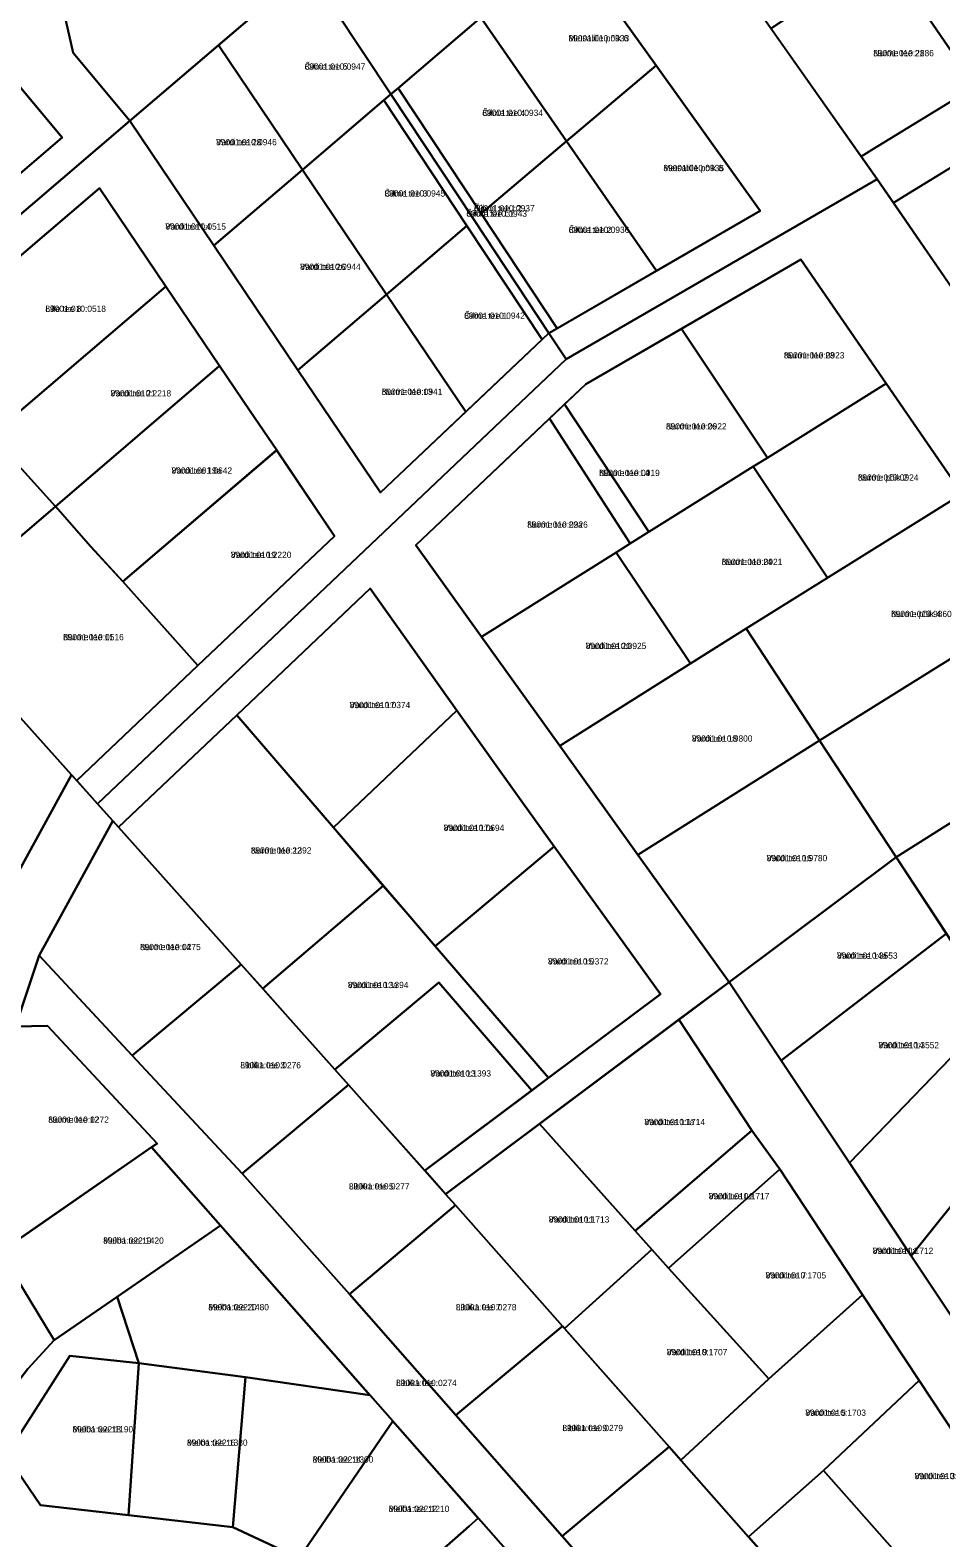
# Model space of a CAD drawing. Extents: x 526849 to 562296, y 6591741 to 6618546.
# Drawn here: x 546028.2 to 546246.1, y 6598458.8 to 6598819.9 of the extents above; entities that cross this region are included whole.
import ezdxf

# ---------------------------------------------------------------- set-up
doc = ezdxf.new("R2010")
doc.units = 0
for name, color, linetype in [('L_AADRESS', 7, 'Continuous'), ('PIIR', 7, 'Continuous'), ('TUNNUS', 7, 'Continuous')]:
    doc.layers.add(name, color=color, linetype=linetype)

msp = doc.modelspace()

# ---------------------------------------------------------------- linework, layer by layer
at = {"layer": 'PIIR'}
for points in [[(546227.01, 6598789.61), (546229.57, 6598791.18), (546282.53, 6598823.65), (546327.15, 6598851.02), (546371.97, 6598878.5), (546413.8, 6598904.15), (546446.52, 6598936.13), (546471.16, 6598923.58), (546475.1, 6598905.89), (546459.53, 6598913.79), (546427, 6598896.41), (546382.82, 6598869.32), (546336.26, 6598840.76), (546290.19, 6598812.52), (546237.29, 6598780.08), (546234.73, 6598778.51), (546230.83, 6598784.18)], [(546157.01, 6598840.7), (546136.05, 6598869.98), (546155.32, 6598886.44), (546157.6, 6598888.39), (546230.83, 6598784.18), (546227.43, 6598782.21), (546156.45, 6598741.04), (546152.31, 6598747.31), (546202.86, 6598776.63), (546177.96, 6598811.42)], [(546049.75, 6598865.37), (546083.92, 6598825.4), (546052, 6598798.11), (546038.43, 6598814.46), (546029.84, 6598852.51)], [(546232.91, 6598837.74), (546260.42, 6598855.23), (546282.53, 6598823.65), (546254.4, 6598806.4)], [(546094.63, 6598834.56), (546109.76, 6598847.49), (546115.53, 6598852.47), (546136.04, 6598822.87), (546116.2, 6598805.98), (546114.49, 6598804.52)], [(546136.04, 6598822.87), (546157.01, 6598840.7), (546177.96, 6598811.42), (546156.53, 6598793.28)], [(546205.45, 6598820.29), (546207.99, 6598821.9), (546232.91, 6598837.74), (546254.4, 6598806.4), (546229.57, 6598791.18), (546227.01, 6598789.61)], [(546073.21, 6598816.25), (546083.92, 6598825.4), (546094.63, 6598834.56), (546114.49, 6598804.52), (546112.78, 6598803.06), (546093.31, 6598786.43)], [(545980.81, 6598798.44), (545968.47, 6598812.88), (546021.07, 6598823.26), (546024.59, 6598807.65), (546035.81, 6598794.14), (546006.15, 6598768.79)], [(546116.2, 6598805.98), (546136.04, 6598822.87), (546156.53, 6598793.28), (546136.05, 6598775.95)], [(546052.01, 6598798.12), (546073.21, 6598816.25), (546093.31, 6598786.43), (546072.09, 6598768.32)], [(546156.53, 6598793.28), (546177.96, 6598811.42), (546202.86, 6598776.63), (546178.04, 6598762.24)], [(546093.31, 6598786.43), (546112.78, 6598803.06), (546132.62, 6598773.04), (546113.41, 6598756.6)], [(546114.49, 6598804.52), (546134.33, 6598774.5), (546152.31, 6598747.3), (546150.68, 6598745.76), (546132.62, 6598773.04), (546112.78, 6598803.06)], [(546116.2, 6598805.98), (546136.05, 6598775.95), (546154.26, 6598748.44), (546152.31, 6598747.3), (546134.33, 6598774.5), (546114.49, 6598804.52)], [(545964.57, 6598723.37), (546052.01, 6598798.12), (546072.09, 6598768.32), (546092.21, 6598738.48), (546111.98, 6598709.12), (546152.31, 6598747.3), (546156.45, 6598741.04), (546044.3, 6598634.57), (546039.29, 6598640.15), (546068.3, 6598667.69), (546100.95, 6598698.68), (546087.16, 6598719.3), (546080.77, 6598728.65), (546073.47, 6598739.44), (546060.63, 6598758.5), (546044.77, 6598782.04), (545999.98, 6598743.77), (545969.58, 6598717.8), (545967.72, 6598719.86)], [(546136.05, 6598775.95), (546156.53, 6598793.28), (546178.04, 6598762.24), (546154.26, 6598748.44)], [(546234.73, 6598778.51), (546237.29, 6598780.08), (546262.06, 6598795.27), (546282.53, 6598765.5), (546257.76, 6598750.31), (546255.2, 6598748.75)], [(546072.09, 6598768.32), (546093.31, 6598786.43), (546113.41, 6598756.6), (546092.21, 6598738.48)], [(546044.77, 6598782.04), (546060.63, 6598758.5), (546018.83, 6598722.76), (545999.98, 6598743.77)], [(546113.41, 6598756.6), (546132.62, 6598773.04), (546150.68, 6598745.76), (546132.38, 6598728.44)], [(546184.04, 6598748.37), (546212.59, 6598764.93), (546232.99, 6598735.27), (546204.6, 6598717.48)], [(546018.83, 6598722.76), (546060.63, 6598758.5), (546073.47, 6598739.44), (546034.25, 6598705.79)], [(546092.21, 6598738.48), (546113.41, 6598756.6), (546132.38, 6598728.44), (546111.98, 6598709.12)], [(546156.04, 6598730.26), (546161.12, 6598735.08), (546184.04, 6598748.37), (546204.6, 6598717.48), (546201.21, 6598715.36), (546181.97, 6598703.3), (546176.22, 6598699.69)], [(546042.71, 6598696.15), (546034.25, 6598705.79), (546073.47, 6598739.44), (546080.77, 6598728.65), (546087.16, 6598719.3), (546050.31, 6598687.87)], [(546201.21, 6598715.36), (546204.6, 6598717.48), (546232.99, 6598735.27), (546251.19, 6598708.83), (546218.96, 6598688.7)], [(546120.49, 6598696.55), (546152.42, 6598726.83), (546171.78, 6598696.91), (546168.39, 6598694.79), (546136.2, 6598674.6)], [(546152.42, 6598726.83), (546156.04, 6598730.26), (546176.22, 6598699.69), (546171.78, 6598696.91)], [(545987.89, 6598697.4), (546013.76, 6598719.58), (546018.24, 6598723.42), (546018.83, 6598722.76), (546034.25, 6598705.79), (546003.78, 6598679.71)], [(546050.31, 6598687.87), (546087.09, 6598719.25), (546100.95, 6598698.68), (546068.3, 6598667.69)], [(546168.39, 6598694.79), (546171.78, 6598696.91), (546176.22, 6598699.69), (546181.97, 6598703.3), (546201.21, 6598715.36), (546218.96, 6598688.7), (546199.52, 6598676.55), (546186.22, 6598668.19)], [(546199.52, 6598676.55), (546251.19, 6598708.83), (546269.38, 6598682.37), (546217.07, 6598649.79)], [(546003.78, 6598679.71), (546034.25, 6598705.79), (546042.73, 6598696.16), (546050.31, 6598687.87), (546068.3, 6598667.69), (546039.29, 6598640.15), (546038.02, 6598641.57), (546006.75, 6598676.39)], [(546136.2, 6598674.6), (546168.39, 6598694.79), (546186.22, 6598668.19), (546154.9, 6598648.5)], [(546109.5, 6598686.12), (546130.25, 6598656.95), (546100.71, 6598628.89), (546077.58, 6598655.82)], [(546217.07, 6598649.79), (546269.38, 6598682.37), (546288.13, 6598655.1), (546235.42, 6598621.83)], [(546038.02, 6598641.57), (546020.66, 6598609.85), (546015.38, 6598608.31), (545986.1, 6598657.84), (546006.75, 6598676.39)], [(546154.9, 6598648.5), (546199.52, 6598676.55), (546217.07, 6598649.79), (546173.59, 6598622.4)], [(546049.3, 6598628.97), (546077.58, 6598655.82), (546100.71, 6598628.89), (546112.65, 6598614.99), (546083.83, 6598590.33), (546078.65, 6598596.12)], [(546100.71, 6598628.89), (546130.25, 6598656.95), (546145.95, 6598634.87), (546153.53, 6598624.37), (546125.1, 6598600.5), (546118.04, 6598608.72)], [(546248.72, 6598601.48), (546235.42, 6598621.83), (546288.13, 6598655.1), (546305.36, 6598630.05), (546306.59, 6598628.27), (546249.9, 6598599.66)], [(546173.59, 6598622.4), (546217.07, 6598649.79), (546235.42, 6598621.83), (546195.44, 6598591.91)], [(546078.65, 6598596.12), (546052.58, 6598574.33), (546030.28, 6598598.27), (546047.93, 6598630.51)], [(546153.53, 6598624.37), (546179.04, 6598589.01), (546152.21, 6598568.94), (546125.1, 6598600.5)], [(546195.44, 6598591.91), (546235.39, 6598621.82), (546247.42, 6598603.5), (546207.88, 6598573.16)], [(546083.83, 6598590.33), (546112.65, 6598614.99), (546118.04, 6598608.72), (546125.1, 6598600.5), (546152.21, 6598568.94), (546148.2, 6598565.94), (546125.97, 6598591.81), (546101.07, 6598570.97), (546090.47, 6598582.89)], [(546207.88, 6598573.16), (546247.42, 6598603.5), (546248.74, 6598601.5), (546249.9, 6598599.66), (546259.24, 6598584.94), (546257.16, 6598582.79), (546224.23, 6598548.61), (546209.82, 6598570.25)], [(546058.51, 6598553.28), (546032.29, 6598581.42), (546024.61, 6598581.29), (546030.28, 6598598.27), (546052.58, 6598574.33), (546078.91, 6598546.06), (546104.54, 6598517.19), (546130, 6598488.19), (546155.47, 6598459.19), (546180.94, 6598430.19), (546206.84, 6598400.69), (546200.13, 6598394.54), (546197.92, 6598392.51), (546057.18, 6598552.36)], [(546090.47, 6598582.89), (546104.33, 6598567.3), (546078.91, 6598546.06), (546052.58, 6598574.33), (546078.65, 6598596.12)], [(546101.07, 6598570.97), (546125.97, 6598591.81), (546148.2, 6598565.94), (546122.59, 6598546.77), (546104.33, 6598567.3)], [(546195.44, 6598591.91), (546209.82, 6598570.25), (546224.23, 6598548.61), (546239.02, 6598526.32), (546254.17, 6598503.61), (546270.41, 6598479), (546276.14, 6598470.32), (546269.8, 6598452.15), (546256.14, 6598413.06), (546251.75, 6598400.5), (546242.29, 6598411.22), (546251.52, 6598437.05), (546261.57, 6598465.17), (546240.93, 6598496.48), (546227.38, 6598517.03), (546207.55, 6598547.12), (546200.89, 6598556.34), (546183.43, 6598582.93)], [(546183.43, 6598582.93), (546200.89, 6598556.34), (546172.92, 6598532.37), (546150.01, 6598557.93)], [(546259.24, 6598584.94), (546264.35, 6598576.9), (546271.03, 6598566.37), (546269.17, 6598564.03), (546239.02, 6598526.32), (546224.23, 6598548.61), (546257.16, 6598582.79)], [(546032.29, 6598581.42), (546058.51, 6598553.28), (546057.18, 6598552.36), (546014.49, 6598522.72), (546012.76, 6598525.17), (546006.45, 6598534.13), (546024.61, 6598581.29)], [(546127.59, 6598541.15), (546129.97, 6598538.45), (546104.54, 6598517.19), (546078.91, 6598546.06), (546104.33, 6598567.3)], [(546271.03, 6598566.37), (546272.94, 6598563.37), (546282.83, 6598547.79), (546281.35, 6598545.51), (546254.17, 6598503.61), (546239.02, 6598526.32), (546269.17, 6598564.03)], [(546150.01, 6598557.93), (546172.92, 6598532.37), (546176.92, 6598527.9), (546156.05, 6598508.92), (546155.52, 6598509.52), (546129.97, 6598538.45), (546127.59, 6598541.15)], [(546200.89, 6598556.34), (546207.55, 6598547.12), (546180.92, 6598523.43), (546176.92, 6598527.9), (546172.92, 6598532.37)], [(546022.61, 6598524.73), (546021.05, 6598527.28), (546057.18, 6598552.36), (546073.68, 6598533.63), (546048.98, 6598516.56), (546033.92, 6598506.14)], [(546207.55, 6598547.12), (546227.38, 6598517.03), (546204.96, 6598496.88), (546180.92, 6598523.43)], [(546155.52, 6598509.52), (546130, 6598488.19), (546104.54, 6598517.19), (546129.97, 6598538.45)], [(546048.98, 6598516.56), (546070.82, 6598531.65), (546073.68, 6598533.63), (546109.43, 6598493), (546079.68, 6598497.29), (546054.12, 6598500.62)], [(545981.81, 6598495.2), (545979.46, 6598498.39), (546021.05, 6598527.28), (546022.61, 6598524.73), (546033.92, 6598506.14), (546027.6, 6598499.26), (546020.97, 6598490.65), (546016.42, 6598482.08), (546008.1, 6598480.34), (545993.08, 6598479.92)], [(546176.92, 6598527.9), (546180.92, 6598523.43), (546204.96, 6598496.88), (546183.84, 6598477.43), (546181.06, 6598480.58), (546156.05, 6598508.92)], [(546227.38, 6598517.03), (546240.93, 6598496.48), (546218.05, 6598474.95), (546200.06, 6598459.06), (546183.84, 6598477.43), (546204.96, 6598496.88)], [(546181.06, 6598480.58), (546155.47, 6598459.19), (546130, 6598488.19), (546155.52, 6598509.52)], [(546030.65, 6598466.68), (546022.46, 6598478.59), (546037.62, 6598502.4), (546054.12, 6598500.62), (546051.67, 6598464.23)], [(546054.12, 6598500.62), (546079.68, 6598497.29), (546076.65, 6598461.35), (546051.67, 6598464.23)], [(546079.68, 6598497.29), (546109.43, 6598493), (546114.91, 6598486.77), (546113.01, 6598483.99), (546092.53, 6598453.94), (546076.65, 6598461.35)], [(546240.93, 6598496.48), (546261.57, 6598465.17), (546251.52, 6598437.05), (546218.05, 6598474.95)], [(546133.21, 6598461.6), (546106.49, 6598438.07), (546092.53, 6598453.94), (546113.01, 6598483.99), (546114.91, 6598486.77), (546135.38, 6598463.52)], [(546206.6, 6598451.65), (546180.94, 6598430.19), (546155.47, 6598459.19), (546181.06, 6598480.58)], [(546218.05, 6598474.95), (546251.52, 6598437.05), (546242.29, 6598411.22), (546231.57, 6598423.36), (546206.6, 6598451.65), (546200.06, 6598459.06)], [(546106.49, 6598438.07), (546133.21, 6598461.6), (546135.38, 6598463.52), (546151.71, 6598444.98), (546149.65, 6598443.15), (546123, 6598419.53)]]:
    msp.add_lwpolyline(points, close=True, dxfattribs=at)
for points in [[(546029.84, 6598852.51), (546038.43, 6598814.46), (546052.01, 6598798.12), (545964.57, 6598723.37), (545961.06, 6598727.61), (545967.39, 6598735.66), (545980.05, 6598746.48), (545955.23, 6598776.56), (545956.94, 6598778.02), (545958.65, 6598779.48), (545983.47, 6598749.4), (546006.15, 6598768.79), (546035.81, 6598794.14), (546024.59, 6598807.65), (546021.07, 6598823.26)], [(546251.19, 6598708.83), (546232.99, 6598735.27), (546212.59, 6598764.93), (546161.12, 6598735.08), (546120.49, 6598696.55), (546136.2, 6598674.6), (546154.9, 6598648.5), (546173.59, 6598622.4), (546195.44, 6598591.91), (546127.59, 6598541.15), (546122.59, 6598546.77), (546152.21, 6598568.94), (546179.04, 6598589.01), (546153.53, 6598624.37), (546145.95, 6598634.87), (546130.25, 6598656.95), (546109.5, 6598686.12), (546077.58, 6598655.82), (546049.3, 6598628.97), (546044.3, 6598634.57), (546156.45, 6598741.04), (546227.43, 6598782.21), (546230.83, 6598784.18), (546329.96, 6598640.07)], [(545888.25, 6598451.38), (545941.12, 6598488.17), (545951.86, 6598495.45), (545980.7, 6598515.7), (545993.05, 6598536.63), (546013.82, 6598593.94), (546020.66, 6598609.85), (546038.02, 6598641.57), (546044.3, 6598634.57), (546047.93, 6598630.51), (546030.28, 6598598.27), (546024.61, 6598581.29), (546006.45, 6598534.13), (545998.6, 6598513.73), (545997.52, 6598510.93), (545942.78, 6598472.92), (545920.83, 6598457.67)], [(546018.7, 6598458.57), (546008.1, 6598480.34), (546016.42, 6598482.08), (546020.97, 6598490.65), (546027.6, 6598499.26), (546033.92, 6598506.14), (546048.98, 6598516.56), (546054.12, 6598500.62), (546037.62, 6598502.4), (546022.46, 6598478.59), (546030.65, 6598466.68), (546051.67, 6598464.23), (546076.65, 6598461.35), (546092.53, 6598453.94)]]:
    msp.add_lwpolyline(points, dxfattribs=at)

# ---------------------------------------------------------------- texts
at = {"layer": 'L_AADRESS'}
for s, p in [('Metsalille põik 6', (546157, 6598817.18)), ('Nurme tee 21', (546229.93, 6598813.62)), ('Õilme tee 5', (546093.85, 6598810.39)), ('Õilme tee 4', (546136.37, 6598799.31)), ('Vardi tee 28', (546072.66, 6598792.29)), ('Metsalille põik 8', (546179.7, 6598786.1)), ('Õilme tee 3', (546112.96, 6598780.02)), ('Õilme tee L2', (546134.38, 6598776.46)), ('Vardi tee L4', (546060.51, 6598772.09)), ('Õilme tee L1', (546132.55, 6598775.18)), ('Õilme tee 2', (546157.04, 6598771.3)), ('Vardi tee 26', (546092.75, 6598762.45)), ('Lille tee 8', (546031.79, 6598752.4)), ('Õilme tee 1', (546132.04, 6598750.74)), ('Nurme tee 28', (546208.52, 6598741.25)), ('Nurme tee 13', (546112.3, 6598732.53)), ('Vardi tee 21', (546047.39, 6598732.15)), ('Nurme tee 26', (546180.32, 6598724.24)), ('Vardi tee 19a', (546061.98, 6598713.66)), ('Nurme tee L4', (546164.32, 6598713.08)), ('Nurme põik 2', (546226.24, 6598711.99)), ('Nurme tee 22a', (546147.1, 6598700.71)), ('Vardi tee 19', (546076.17, 6598693.47)), ('Nurme tee 24', (546193.66, 6598691.78)), ('Nurme põik 4', (546234.2, 6598679.31)), ('Nurme tee 11', (546036.04, 6598673.77)), ('Vardi tee 20', (546161.11, 6598671.65)), ('Vardi tee 17', (546104.61, 6598657.51)), ('Vardi tee 18', (546186.51, 6598649.48)), ('Vardi tee 17a', (546127.12, 6598628.09)), ('Nurme tee 22', (546080.97, 6598622.69)), ('Vardi tee 16', (546204.41, 6598620.85)), ('Nurme tee 14', (546054.46, 6598599.55)), ('Vardi tee 15', (546152.07, 6598596.12)), ('Vardi tee 14a', (546221.24, 6598597.49)), ('Vardi tee 13a', (546104.18, 6598590.46)), ('Vardi tee 14', (546231.16, 6598576.05)), ('Liblika tee 3', (546078.45, 6598571.25)), ('Vardi tee 13', (546123.94, 6598569.29)), ('Nurme tee 12', (546032.48, 6598558.21)), ('Vardi tee 11a', (546175.15, 6598557.65)), ('Liblika tee 5', (546104.44, 6598542.24)), ('Vardi tee L2', (546190.55, 6598539.88)), ('Vardi tee 11', (546152.26, 6598534.32)), ('Melba tee 19', (546045.62, 6598529.25)), ('Vardi tee L1', (546229.79, 6598526.81)), ('Vardi tee 7', (546204.15, 6598520.93)), ('Melba tee 20', (546070.79, 6598513.32)), ('Liblika tee 7', (546130.03, 6598513.3)), ('Vardi tee 9', (546180.5, 6598502.55)), ('Liblika tee', (546115.73, 6598495.16)), ('Vardi tee 5', (546213.67, 6598488.04)), ('Melba tee 18', (546038.29, 6598484.06)), ('Liblika tee 9', (546155.53, 6598484.37)), ('Melba tee 16', (546065.68, 6598480.86)), ('Melba tee 14', (546095.78, 6598476.84)), ('Vardi tee 3', (546239.81, 6598472.87)), ('Melba tee 12', (546113.96, 6598465.01))]:
    msp.add_text(s, height=1.5, dxfattribs=at).set_placement(p)
at = {"layer": 'TUNNUS'}
for s, p in [('89001:010:0933', (546157, 6598817.18)), ('89001:010:2886', (546229.93, 6598813.62)), ('89001:010:0947', (546093.85, 6598810.39)), ('89001:010:0934', (546136.37, 6598799.31)), ('89001:010:0946', (546072.66, 6598792.29)), ('89001:010:0935', (546179.7, 6598786.1)), ('89001:010:0945', (546112.96, 6598780.02)), ('89001:010:0937', (546134.38, 6598776.46)), ('89001:010:0943', (546132.55, 6598775.18)), ('89001:010:0515', (546060.51, 6598772.09)), ('89001:010:0936', (546157.04, 6598771.3)), ('89001:010:0944', (546092.75, 6598762.45)), ('89001:010:0518', (546031.79, 6598752.4)), ('89001:010:0942', (546132.04, 6598750.74)), ('89001:010:0923', (546208.52, 6598741.25)), ('89001:010:0941', (546112.3, 6598732.53)), ('89001:010:2218', (546047.39, 6598732.15)), ('89001:010:0922', (546180.32, 6598724.24)), ('89001:001:0642', (546061.98, 6598713.66)), ('89001:010:0919', (546164.32, 6598713.08)), ('89001:010:0924', (546226.24, 6598711.99)), ('89001:010:0926', (546147.1, 6598700.71)), ('89001:010:2220', (546076.17, 6598693.47)), ('89001:010:0921', (546193.66, 6598691.78)), ('89001:010:9860', (546234.2, 6598679.31)), ('89001:010:0516', (546036.04, 6598673.77)), ('89001:010:0925', (546161.11, 6598671.65)), ('89001:010:0374', (546104.61, 6598657.51)), ('89001:010:9800', (546186.51, 6598649.48)), ('89001:010:0694', (546127.12, 6598628.09)), ('89001:010:1392', (546080.97, 6598622.69)), ('89001:010:9780', (546204.41, 6598620.85)), ('89001:010:0275', (546054.46, 6598599.55)), ('89001:010:0372', (546152.07, 6598596.12)), ('89001:010:3553', (546221.24, 6598597.49)), ('89001:010:1394', (546104.18, 6598590.46)), ('89001:010:3552', (546231.16, 6598576.05)), ('89001:010:0276', (546078.45, 6598571.25)), ('89001:010:1393', (546123.94, 6598569.29)), ('89001:010:0272', (546032.48, 6598558.21)), ('89001:010:1714', (546175.15, 6598557.65)), ('89001:010:0277', (546104.44, 6598542.24)), ('89001:010:1717', (546190.55, 6598539.88)), ('89001:010:1713', (546152.26, 6598534.32)), ('89001:022:1420', (546045.62, 6598529.25)), ('89001:010:1712', (546229.79, 6598526.81)), ('89001:010:1705', (546204.15, 6598520.93)), ('89001:022:1480', (546070.79, 6598513.32)), ('89001:010:0278', (546130.03, 6598513.3)), ('89001:010:1707', (546180.5, 6598502.55)), ('89001:010:0274', (546115.73, 6598495.16)), ('89001:010:1703', (546213.67, 6598488.04)), ('89001:022:1190', (546038.29, 6598484.06)), ('89001:010:0279', (546155.53, 6598484.37)), ('89001:022:1380', (546065.68, 6598480.86)), ('89001:022:1300', (546095.78, 6598476.84)), ('89001:010:1702', (546239.81, 6598472.87)), ('89001:022:1210', (546113.96, 6598465.01))]:
    msp.add_text(s, height=1.5, dxfattribs=at).set_placement(p)

doc.saveas('drawing.dxf')
